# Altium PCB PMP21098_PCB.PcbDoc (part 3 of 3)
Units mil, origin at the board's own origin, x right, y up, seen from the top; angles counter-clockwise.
Board outline 5551.18 x 2125.98 mil, 4 copper layers (Top Layer, Signal Layer 1, Signal Layer 2, Bottom Layer), stack 61.6 mil thick; 197 components, 100 nets, 482 pads, 134 vias.
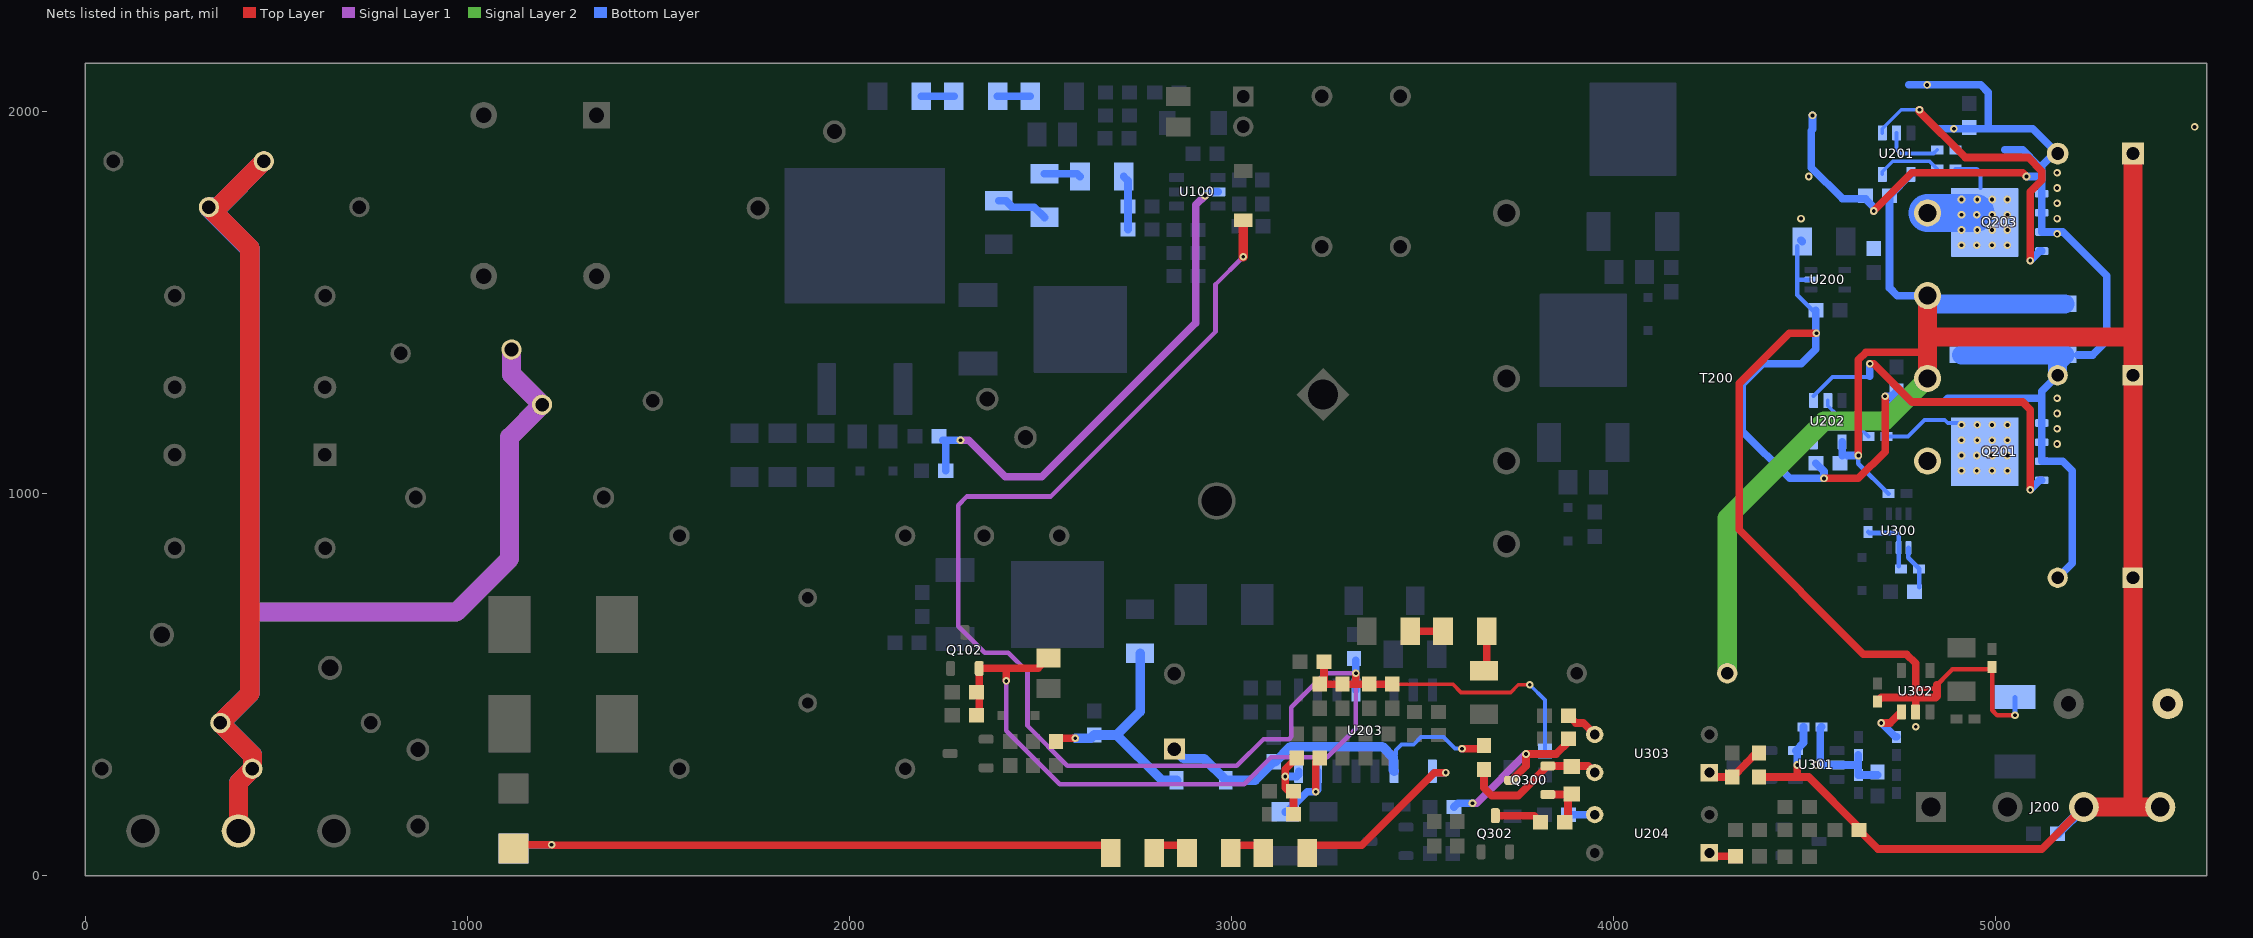
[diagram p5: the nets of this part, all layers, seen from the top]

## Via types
v1: diameter 20, hole 10, Top Layer to Bottom Layer, 134 vias

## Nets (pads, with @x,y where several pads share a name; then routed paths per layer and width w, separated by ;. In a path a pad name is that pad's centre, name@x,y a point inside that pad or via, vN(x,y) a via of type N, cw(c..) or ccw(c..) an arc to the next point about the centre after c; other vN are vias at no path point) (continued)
NetQ201_5: Q201.5 Q201.6 Q201.7 Q201.8 Q201.9@4970.43,1110 R203.2 T200.8 | length 207.1
  Bottom Layer w10: R203.2@4713.62,1150 4770,1150 4812.61,1192.61 4866.13,1192.61 4873.74,1185 Q201.8@4899.96,1185
  other v1: 4910,1060 4950,1060 4990,1060 5030,1060 4910,1100 4950,1100 4990,1100 5030,1100 4910,1140 4951.1,1140 4990,1140 5030,1140 4910,1180 4951.1,1180 4990,1180 5030,1180
NetQ203_5: Q203.5 Q203.6 Q203.7 Q203.8 Q203.9@4970.43,1710 R206.1 T200.11 | length 235
  Bottom Layer w10: R206.1@4893.62,1850 4950,1850 4960,1840 4960,1800
  Bottom Layer w100: T200.11@4821.18,1734.8 Q203.9@4945.63,1734.8
  other v1: 4910,1650 4950,1650 4990,1650 5030,1650 4910,1690 4951.1,1690 4990,1690 5030,1690 4910,1730 4950,1730 4990,1730 5030,1730 4910,1770 4951.1,1770 4990,1770 5030,1770
NetQ300_1: Q300.1 R309.1 R311.2 | length 139.5
  Top Layer w20: Q300.1@3827.24,212.6 R309.1@3884.09,212.6 ; R311.2@3880,140 3880,208.5 R309.1@3884.09,212.6 ; R309.1@3890,218.5 R309.1@3884.09,212.6
NetQ300_2: Q300.2 R304.2 R309.2 U303.4 | length 385.8
  Top Layer w20: R304.2@3660,278.5 3660,230.45 3680.45,210 3749.84,210 Q300.2@3827.24,287.4 3932.6,287.4 U303.4@3950,270
NetQ300_3: Q300.3 R313.1 R315.2 | length 462.6
  Top Layer w20: Q300.3@3732.93,250 Q300.3@3732.76,250 3770,287.24 v1(3770,318.9) 3848.9,318.9 3881.5,351.5 R315.2@3881.5,358.54
  Signal Layer 1 w20: v1(3630,190) 3641.1,190 v1(3770,318.9)
  Bottom Layer w20: R313.1@3581.5,180 3591.5,190 v1(3630,190)
NetQ302_3: Q302.3 R311.1 | length 125.6
  Top Layer w20: Q302.3@3690,157.24 3791.26,157.24 R311.1@3808.5,140
NetR100_1: R100.1 R101.2 | length 85.8
  Bottom Layer w20: R100.1@2187.09,2040 R101.2@2272.91,2040
NetR101_1: R101.1 R105.2 | length 85.8
  Bottom Layer w20: R101.1@2387.09,2040 R105.2@2472.91,2040
NetR102_1: R102.1 R107.1 U100.5 | length 1322
  Signal Layer 1 w20: v1(2290,1140) 2311.87,1140 2407.51,1044.36 2503.2,1044.36 2905.75,1446.91 2905.75,1755.75 v1(2930,1780)
  Bottom Layer w20: R102.1@2244.03,1140 v1(2290,1140) ; R107.1@2251.5,1060 R102.1@2251.5,1132.53 ; v1(2930,1780) 2940,1790 U100.5@2964.13,1790
NetR106_1: R106.1 R109.2 | length 138.3
  Bottom Layer w20: R106.1@2390,1767.09 2409.17,1767.09 2426.26,1750 2482.91,1750 R109.2@2510,1722.91
NetR109_1: R109.1 R115.2 | length 95.8
  Bottom Layer w20: R109.1@2510,1837.09 2595.83,1837.09 R115.2@2602.91,1830
NetR115_1: R115.1 R117.2 R118.2 | length 143.3
  Bottom Layer w20: R115.1@2717.09,1830 2728.5,1818.58 R118.2@2728.5,1751.46 R117.2@2728.5,1691.46
NetR214_1: R214.1 R220.2 | length 85.8
  Top Layer w20: R214.1@3467.09,640 R220.2@3552.91,640
NetR216_1: R216.1 U204.1 | length 59.6
  Top Layer w20: U204.1@4258.9,51.1 R216.1@4318.5,51.1
NetR217_1: R217.1 R218.2 | length 85.8
  Top Layer w20: R217.1@2797.09,80 R218.2@2882.91,80
NetR218_1: R218.1 R219.2 | length 85.8
  Top Layer w20: R218.1@2997.09,80 R219.2@3082.91,80
NetR219_1: R219.1 U203.1 | length 472.9
  Top Layer w20: R219.1@3197.09,80 3340,80 3530,270 v1(3560,270)
  Bottom Layer w20: U203.1@3528.7,270 v1(3560,270)
NetR220_1: R220.1 R223.2 | length 95.8
  Top Layer w20: R223.2@3667.09,544.17 R220.1@3667.09,640
NetR226_2: R226.2 U204.3 | length 68.5
  Bottom Layer w20: R226.2@3881.5,160 U204.3@3950,160
NetR300_2: R300.2 R301.2 U300.1 | length 116.2
  Bottom Layer w12: U300.1@4771.2,858.97 4771.2,841.2 4770,840 4770,832.5 R301.2@4799.23,803.27 R300.2@4799.23,755.39
NetR303_1: R303.1 R305.2 U303.1 | length 138
  Top Layer w20: U303.1@4261.5,258.5 R305.2@4310,258.5 4310.67,258.5 4346.57,294.41 4346.57,295.08 R303.1@4372.99,321.5
NetR310_1: R310.1 U302.1 | length 119.7
  Top Layer w20: v1(4700,400) 4723.58,400 U302.1@4752.6,429.02
  Bottom Layer w20: v1(4700,400) 4736.38,363.62 R310.1@4740,363.62
NetR316_2: R316.2 U303.3 | length 88.6
  Top Layer w20: R316.2@3881.5,418.54 3900.04,400 3920,400 U303.3@3950,370
OV: C234.1 R210.1 R211.2 U203.8 | length 207.2
  Top Layer w20: R210.1@3161.5,161.3 3161.5,208.5 3140,230 v1(3140,260) 3140,278.5 C234.1@3170,308.5
  Bottom Layer w20: v1(3140,260) U203.8@3170,260 ; U203.8@3175,265 U203.8@3175,273.7
PE: C100.2 C101.2 C102.2 C110.1 C111.1 C112.1 TP_PE.1 | length 10649.3
  Top Layer w50: C111.1@323.15,1750 430,1643.15 430,476.85 C110.1@353.15,400 436.85,316.3 C100.2@436.85,280 400.13,243.28 TP_PE.1@400.13,117.51 ; C111.1@346.85,1750 C101.2@466.85,1870
  Signal Layer 1 w50: TP_PE.1@400.13,117.51 400.13,243.28 C100.2@436.85,280 436.85,316.3 C110.1@353.15,400 430,476.85 430,680 ; C101.2@466.85,1870 346.85,1750 C111.1@323.15,1750 430,1643.15 430,680 ; C112.1@1115.02,1377.33 1115.02,1312.63 C102.2@1194.98,1232.67 1110,1147.69 1110,830 970,690 440,690 430,680
  Signal Layer 2 w50: TP_PE.1@400.13,117.51 400.13,243.28 C100.2@436.85,280 436.85,316.3 C110.1@353.15,400 430,476.85 430,690 ; C101.2@466.85,1870 346.85,1750 C111.1@323.15,1750 430,1643.15 430,690 ; C112.1@1115.02,1377.33 1115.02,1312.63 C102.2@1194.98,1232.67 1110,1147.69 1110,830 970,690 430,690
  Bottom Layer w50: C111.1@323.15,1750 323.15,1746.85 430,1640 430,476.85 C110.1@353.15,400 436.85,316.3 C100.2@436.85,280 400.13,243.28 TP_PE.1@400.13,117.51 ; C111.1@346.85,1750 C101.2@466.85,1870 ; C112.1@1115.02,1377.33 1115.02,1312.63 C102.2@1194.98,1232.67
RVCC: C116.1 C117.1 C228.1 C229.1 C230.1 C231.1 D109.2 Q102.2 R111.2 R212.1 R215.2 R225.2 U203.12 | length 5475.6
  Top Layer w10: C231.1@3420,501.5 3578.5,501.5 3600,480 3730,480 3750,500 v1(3780,500)
  Top Layer w20: R111.2@2339.05,427.56 Q102.2@2339.05,542.76 2410,542.76 ; v1(2410,510) 2410,542.76 ; C117.1@2520,570 2492.76,542.76 2410,542.76 ; 3241.5,540 3241.5,512.99 C228.1@3230,501.5 C229.1@3290,501.5 3325,501.5 ; v1(3325,530) 3325,501.5 ; C231.1@3420,501.5 C230.1@3360,501.5 3325,501.5
  Top Layer w25: v1(3030,1620) D109.2@3030,1715.53
  Signal Layer 1 w12: v1(2410,510) 2410,380 2550,240 3032.92,240 3102.79,309.87 3250,309.87 3325,384.87 v1(3325,530) 3245.12,530 3156.13,441.01 3156.13,363.75 3150,357.62 3083.01,357.62 3013.14,287.75 2569.78,287.75 2465.35,392.18 2465.35,533.84 2415.31,583.87 2353.31,583.87 2283.87,653.31 2283.87,970.11 2306.38,992.61 2526.38,992.61 2957.5,1423.73 2957.5,1547.5 v1(3030,1620)
  Bottom Layer w10: v1(3780,500) 3820,460 R215.2@3820,326.76
  Bottom Layer w20: U203.12@3325,486.3 v1(3325,530) R212.1@3325,563.5
SGND: C200.2 C202.1 C203.1 C204.2 C208.2 C209.2 C210.2 C211.2 C212.2 C216.2 C217.2 C218.2 C219.2 C300.2 C301.2 C303.2 C304.2 C305.2 Q201.1 Q201.2 Q201.3 Q203.1 Q203.2 Q203.3 R204.2 R207.1 R209.1 R301.1 R307.2 R312.1 U200.2 U300.2 U301.2 U302.2 | length 7503.4
  Top Layer w12: 4790,490 4835.46,490 4885.46,540 4983.62,540 R307.2@4990,546.38 4990,432.91 5002.91,420 v1(5050,420)
  Top Layer w20: v1(4530,1420) 4459.42,1420 4327.87,1288.45 4327.87,905.17 4653.04,580 4765.83,580 4790,555.83 4790,490 ; v1(4550,1040) 4640,1040 4710,1110 v1(4710,1255) ; v1(4680,1740) 4780,1840 5070,1840 v1(5080,1830) ; C305.2@4690,456.38 4700.2,466.57 4790,466.57 ; U302.2@4790,429.02 4790,466.57 ; 4845.59,499.87 4845.59,469.87 4842.29,466.57 4790,466.57
  Bottom Layer w12: C204.2@4480,1647.09 4480,1560 ; U200.2@4515.71,1560 4480,1560 ; C200.2@4528.5,1480 4520,1480 4480,1520 4480,1560 ; C300.2@4665.61,899.64 4668.18,897.08 4740,897.08 4745.61,891.47 U300.2@4745.61,858.97 R301.1@4745.61,809.64 ; v1(5050,420) R209.1@5050,467.4
  Bottom Layer w20: C204.2@4490,1662.91 C204.2@4492.91,1660 ; 4516.38,1950 4516.38,1853.62 4598.5,1771.5 4658.5,1771.5 4680,1750 v1(4680,1740) ; 4520,1953.62 v1(4520,1990) ; C219.2@4528.5,1080 4550,1058.5 v1(4550,1040) 4460,1040 4336.38,1163.62 4336.38,1286.38 4390,1340 4490,1340 4528.5,1378.5 C200.2@4528.5,1480 ; C301.2@4543.62,390 4540,386.38 4540,300 4550,290 U301.2@4584.13,290 4638,290 ; C304.2@4640,316.38 C303.2@4640,263.62 R312.1@4690,263.62 ; v1(4710,1255) 4726.5,1255 C218.2@4740,1268.5 4768.82,1239.68 ; 4730.31,1239.68 4768.82,1239.68 ; 4771.5,2070 v1(4820,2070) 4960,2070 4980,2050 4980,1955 ; 4847.28,1955 4980,1955 ; 5023.62,1900 5070,1900 5110,1860 ; v1(5080,1830) 5120.04,1830 ; C208.2@5151.57,1890 5120.04,1858.46 5120.04,1830 ; C210.2@5161.57,780 5200,818.43 5200,1060 5175,1085 Q201.3@5120.04,1085 Q201.2@5120.04,1135 Q201.1@5120.04,1185 5120.04,1250 ; C209.2@5161.57,1310 5120.04,1268.46 5120.04,1250 ; C208.2@5161.57,1890 5096.57,1955 4980,1955 ; 5214.65,1363.07 5253.07,1363.07 5290,1400 5290,1570 5175,1685 Q203.3@5120.04,1685 Q203.2@5120.04,1735 Q203.1@5120.04,1785 5120.04,1830 ; 4768.82,1239.68 4811.97,1239.68 4863.31,1239.68 4873.62,1250 5120.04,1250
  Bottom Layer w50: C202.1@4910,1363.07 C203.1@5000,1363.07 C211.2@5090,1363.07 C212.2@5180,1363.07 5161.57,1344.65 C209.2@5161.57,1310
  other v1: 4530,290 4790,390 5160,1130 5160,1170 5160,1210 5160,1250 5160,1680 4490,1720 5160,1720 5160,1760 5160,1800 4510,1830 5160,1840 4890,1955 5520,1960
VCC: C223.2 D205.2 R120.1 R231.1 | length 599.5
  Top Layer w20: R120.1@2548.5,360 v1(2590.26,360)
  Bottom Layer w25: v1(2590.26,360) 2631.5,360 C223.2@2640,368.5 2698.5,368.5 ; R231.1@2760,582.91 2760,430 2698.5,368.5 ; D205.2@2855.53,250 2817.01,250 2698.5,368.5
VCC_IC: C224.2 C226.1 D205.1 R304.1 U203.3 | length 961.9
  Top Layer w20: v1(3602.49,332.49) R304.1@3651,332.49
  Bottom Layer w10: 3422.5,310 3430,317.5 3430,329.47 3444.26,343.73 3476.27,343.73 3495.4,362.87 3554.6,362.87 3584.6,332.87 3589.93,332.87 3590.31,332.49 v1(3602.49,332.49)
  Bottom Layer w20: C224.2@3110,298.5 C224.2@3110.67,298.5
  Bottom Layer w25: C226.1@2850,331.57 2875.41,306.16 2928.31,306.16 D205.1@2984.47,250 3061.5,250 C224.2@3110,298.5 ; C224.2@3110.67,298.5 3114.21,298.5 3153.94,338.23 3394.27,338.23 3422.5,310 3422.5,276.2 U203.3@3425,273.7
VCR: C207.2 C233.1 U203.7 | length 250.3
  Top Layer w20: v1(3220,220) 3220,298.5 C233.1@3230,308.5
  Bottom Layer w20: C207.2@3140,167.09 3144.57,167.09 3197.48,220 v1(3220,220) 3225,225 U203.7@3225,273.7
VD_SR1: R206.2 U201.5 | length 170.1
  Bottom Layer w10: U201.5@4702.6,1835.87 4702.6,1842.6 4730,1870 4826.38,1870 R206.2@4846.38,1850
VD_SR2: R203.1 U202.5 | length 170.1
  Bottom Layer w10: U202.5@4522.6,1135.87 4522.6,1142.6 4550,1170 4646.38,1170 R203.1@4666.38,1150
VG_SR1: Q203.4 U201.1 | length 805.6
  Top Layer w20: v1(4799.81,2005) 4799.81,2000.19 4920,1880 5084.27,1880 5120.04,1844.23 5120.04,1820.04 5090,1790 v1(5090,1610)
  Bottom Layer w10: U201.1@4702.6,1944.13 4702.6,1955.26 4752.34,2005 v1(4799.81,2005)
  Bottom Layer w20: v1(5090,1610) 5115,1635 Q203.4@5120.04,1635
VG_SR2: Q201.4 U202.1 | length 917.7
  Top Layer w20: v1(4670,1340) 4680,1340 4780,1240 5070,1240 5090,1220 v1(5090,1010)
  Bottom Layer w10: U202.1@4522.6,1255.26 4572.34,1305 4667.28,1305
  Bottom Layer w20: 4670,1307.72 v1(4670,1340) ; v1(5090,1010) 5115,1035 Q201.4@5120.04,1035
Vout: C202.2 C203.2 C208.1 C209.1 C210.1 C211.1 C212.1 C213.2 C215.1 C217.1 C219.1 C301.1 J200.3 J200.4 R202.2 R213.1 R302.1 R303.2 T200.9 T200.10 TP200.1 U201.4 U202.4 U301.5 | length 6377.8
  Top Layer w20: R303.2@4380,258.5 4480,258.5 ; v1(4480,290) 4480,258.5 ; v1(4640,1100) 4640,1350 4660,1370 4821.18,1370 ; J200.3@5230,180 5120,70 4691.5,70 R213.1@4641.5,120 4641.5,127.05 4510.04,258.5 4480,258.5
  Top Layer w50: T200.9@4821.18,1301.73 4821.18,1370 4821.18,1410 ; T200.10@4821.18,1518.27 4821.18,1410 ; J200.3@5230,180 J200.4@5430,180 ; 5348.43,1410 4821.18,1410 ; 5358.43,181.57 C210.1@5358.43,780 C209.1@5358.43,1310 C208.1@5358.43,1890
  Signal Layer 2 w50: C215.1@4296.85,530 4296.85,936.85 4550,1190 4709.45,1190 T200.9@4821.18,1301.73
  Bottom Layer w12: v1(4640,1100) 4640,1078.82 R302.1@4718.82,1000
  Bottom Layer w20: U301.5@4475.87,327.4 4496.38,347.91 C301.1@4496.38,390 ; v1(4480,290) U301.5@4480,323.27 ; 4597.4,1100 U202.4@4597.4,1135.87 ; 4611.5,1100 v1(4640,1100) ; C217.1@4721.5,1780 4721.5,1538.5 4741.73,1518.27 T200.10@4821.18,1518.27 ; C217.1@4721.5,1780 U201.4@4777.4,1835.87
  Bottom Layer w25: C213.2@5161.5,110 J200.3@5230,178.5
  Bottom Layer w50: T200.10@4821.18,1518.27 4842.52,1496.93 C202.2@4910,1496.93 C203.2@5000,1496.93 C211.1@5090,1496.93 C212.1@5180,1496.93
VS_SR1: R207.2 U201.2 | length 158.8
  Bottom Layer w10: U201.2@4740,1944.13 4740,1900 4750,1890 4836.38,1890 R207.2@4846.38,1900
VS_SR2: R204.1 U202.2 | length 132.9
  Bottom Layer w10: U202.2@4560,1244.13 4560,1230 4585,1205 4661.38,1205 R204.1@4666.38,1200
XCAP: D106.1 D107.1 R217.2 | length 1641.7
  Top Layer w20: D107.1@1130,81.26 v1(1220,81.26) ; v1@1221.26,80 R217.2@2682.91,80
  Bottom Layer w20: D106.1@1130,81.26 v1(1220,81.26)
pads on no net: L100.4 L100.6 Q201.9@4954.88,1052.91 Q201.9@4954.88,1110 Q201.9@4954.88,1167.09 Q201.9@4988.35,1110 Q201.9@5024.96,1052.91 Q201.9@5024.96,1110 Q201.9@5024.96,1167.09 Q203.9@4954.88,1652.91 Q203.9@4954.88,1710 Q203.9@4954.88,1767.09 Q203.9@4988.35,1710 Q203.9@5024.96,1652.91 Q203.9@5024.96,1710 Q203.9@5024.96,1767.09 U200.1 U200.3 U300.5

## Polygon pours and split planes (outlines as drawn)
NetC106_2 on Top Layer "C106_2" (solid, remove dead copper, pour order 2): 960,190 930,220 930,480 1030,580 1030,860 1200,1030 1380,1030 1400,1010 1400,940 1240,780 1240,220 1210,190
NetC107_2 on Top Layer "C107_2" (solid, remove dead copper, pour order 10): 1340,750 1320,730 1320,580 1330,570 1520,570 1530,580 1530,730 1510,750
NetC108_2 on Top Layer "C108_2" (solid, remove dead copper, pour order 16): 2160,860 2180,880 2180,1010 2000,1190 2000,1990 1990,2000 1920,2000 1870,1950 1870,1040 2050,860
NetQ203_5 on Top Layer "Q203_5" (solid, remove dead copper, pour order 32): 4810,1810 4770,1770 4770,1610 4800,1580 5040,1580 5060,1600 5060,1800 5050,1810
NetQ201_5 on Top Layer "Q201_5" (solid, remove dead copper, pour order 36): 4790,1210 4770,1190 4770,1010 4790,990 5040,990 5060,1010 5060,1200 5050,1210
IN+ on Top Layer "IN+" (solid, remove dead copper, pour order 44): 4770,120 4750,140 4750,230 4830,310 5060,310 5080,330 5080,400 5180,500 5210,500 5240,470 5240,330 5130,220 5130,140 5110,120
Vout on Top Layer "Vout" (solid, remove dead copper, pour order 54): 4800,1560 4770,1530 4770,1290 4800,1260 5050,1260 5140,1350 5180,1350 5250,1280 5250,320 5150,220 5150,140 5170,120 5520,120 5540,140 5540,1890 5480,1950 5260,1950 5240,1930 5240,1680 5120,1560
SGND on Top Layer "SGND" (solid, remove dead copper, pour order 60): 5540,30 5520,10 4250,10 4230,30 4230,380 4270,420 4270,1300 4460,1490 4460,2080 4490,2110 5520,2110 5540,2090
GND on Top Layer "GND" (solid, remove dead copper, pour order 68): 3970,30 3950,10 3050,10 2870,190 1350,190 1320,220 1320,730 2700,2110 3030,2110 3970,1170
NetC102_1 on Bottom Layer "C102_1" (solid, remove dead copper, pour order 4): 1050,190 1040,200 1040,220 1039.67,220.33 1039.67,690.33 800,930 800,1080 810,1090 970,1090 1240,820 1240,220 1210,190
NetC107_2 on Bottom Layer "C107_2" (solid, remove dead copper, pour order 6): 1340,750 1320,730 1320,580 1330,570 1610,570 1940,240 2170,240 2190,260 2190,300 1740,750
NetC114_2 on Bottom Layer "C113_2" (solid, remove dead copper, pour order 12): 1700,1100 1680,1120 1680,1200 1830,1350 1960,1350 2050,1260 2050,1120 2030,1100
NetC108_2 on Bottom Layer "C108_2" (solid, remove dead copper, pour order 14): 1790,750 1790,730 1870,650 1950,650 2180,880 2180,900 2160,920 1960,920
NetC109_2 on Bottom Layer "C109_2" (solid, remove dead copper, pour order 18): 2280,1290 2260,1310 2260,1350 2150,1460 1740,1460 1650,1550 1650,1880 1870,2100 2085.43,2100 2110,2075.43 2110,1930 2130,1910 2270,1910 2290,1890 2290,1620 2340,1570 2370,1570 2390,1550 2390,1310 2370,1290
HV on Bottom Layer "HV" (solid, remove dead copper, pour order 20): 2350,1690 2340,1680 2340,1630 2380,1590 2410,1590 2440,1560 2440,1300 2560,1180 3260,1180 3490,1410 3490,1640 3670,1820 4190,1820 4210,1840 4210,2090 4190,2110 3670,2110 3314.77,1754.77 3314.77,1484.77 3260,1430 2860,1430 2700,1590 2520,1590 2420,1690
HS on Bottom Layer "HS" (solid, remove dead copper, pour order 22): 3890,1750 3780,1640 3780,1470 3660,1350 3660,1280 3680,1260 4030,1260 4050,1280 4050,1510 4030,1530 4030,1710 3990,1750
Vout on Bottom Layer "Vout" (solid, remove dead copper, pour order 26): 4780,1290 4800,1270 4850,1270 4860,1280 4860,1410 4880,1430 5200,1430 5220,1450 5220,1520 5180,1560 4790,1560 4750,1600 4750,1682.6 4732.6,1700 4600,1700 4590,1690 4590,1580 4595.59,1585.59 4604.41,1585.59 4650,1540 4650,1430 4670,1410 4730,1410 4780,1360
NetQ203_5 on Bottom Layer "Q203_5" (solid, remove dead copper, pour order 28): 4810,1810 4770,1770 4770,1610 4800,1580 5040,1580 5060,1600 5060,1800 5050,1810
NetQ201_5 on Bottom Layer "Q201_5" (solid, remove dead copper, pour order 42): 5060,1010 5060,1200 5050,1210 4890,1210 4860,1180 4833.78,1180 4823.78,1170 4823.78,1150 4821.65,1150 4801.65,1130 4800,1130 4770,1100 4770,1050 4830,990 5040,990
IN+ on Bottom Layer "IN+" (solid, remove dead copper, pour order 46): 4770,120 4750,140 4750,230 4830,310 5060,310 5080,330 5080,400 5180,500 5210,500 5240,470 5240,330 5130,220 5130,140 5110,120
SGND on Bottom Layer "SGND" (solid, remove dead copper, pour order 62): 5540,30 5520,10 4250,10 4230,30 4230,380 4270,420 4270,1300 4460,1490 4460,2080 4490,2110 5520,2110 5540,2090
GND on Bottom Layer "GND" (solid, remove dead copper, pour order 70): 3970,30 3950,10 3050,10 2870,190 1350,190 1320,220 1320,730 2700,2110 3030,2110 3970,1170
NetC103_2 on Bottom Layer "C103_2" (solid, pour order 58): 2420,620 2440,600 2650,600 2660,610 2660,750 2730,820 2950,820 3020,890 3020,1000 2980,1040 2640,1040 2420,820
NetC107_2 on Signal Layer 1 "C107_2" (solid, remove dead copper, pour order 8): 1340,750 1320,730 1320,580 1330,570 1610,570 1940,240 2170,240 2190,260 2190,300 1740,750
NetQ203_5 on Signal Layer 1 "Q203_5" (solid, remove dead copper, pour order 30): 4810,1810 4770,1770 4770,1610 4800,1580 5040,1580 5060,1600 5060,1800 5050,1810
NetQ201_5 on Signal Layer 1 "Q201_5" (solid, remove dead copper, pour order 40): 4790,1210 4770,1190 4770,1010 4790,990 5040,990 5060,1010 5060,1200 5050,1210
IN+ on Signal Layer 1 "IN+" (solid, remove dead copper, pour order 50): 4770,120 4750,140 4750,230 4830,310 5060,310 5080,330 5080,400 5180,500 5210,500 5240,470 5240,330 5130,220 5130,140 5110,120
SGND on Signal Layer 1 "SGND" (solid, remove dead copper, pour order 66): 5540,30 5520,10 4250,10 4230,30 4230,380 4270,420 4270,1300 4460,1490 4460,2080 4490,2110 5520,2110 5540,2090
GND on Signal Layer 1 "GND" (solid, remove dead copper, pour order 74): 3970,30 3950,10 3050,10 2870,190 1350,190 1320,220 1320,730 2700,2110 3030,2110 3970,1170
NetQ203_5 on Signal Layer 2 "Q203_5" (solid, remove dead copper, pour order 34): 4810,1810 4770,1770 4770,1610 4800,1580 5040,1580 5060,1600 5060,1800 5050,1810
NetQ201_5 on Signal Layer 2 "Q201_5" (solid, remove dead copper, pour order 38): 4830,1210 4770,1150 4770,1010 4790,990 5040,990 5060,1010 5060,1200 5050,1210
IN+ on Signal Layer 2 "IN+" (solid, remove dead copper, pour order 48): 4770,120 4750,140 4750,230 4830,310 5060,310 5080,330 5080,400 5180,500 5210,500 5240,470 5240,330 5130,220 5130,140 5110,120
Vout on Signal Layer 2 "Vout" (solid, remove dead copper, pour order 56): 4800,1560 4770,1530 4770,1290 4800,1260 5050,1260 5140,1350 5180,1350 5250,1280 5250,320 5150,220 5150,140 5170,120 5520,120 5540,140 5540,1890 5480,1950 5260,1950 5240,1930 5240,1680 5120,1560
SGND on Signal Layer 2 "SGND" (solid, remove dead copper, pour order 64): 5540,30 5520,10 4250,10 4230,30 4230,380 4270,420 4270,1300 4460,1490 4460,2080 4490,2110 5520,2110 5540,2090
GND on Signal Layer 2 "GND" (solid, remove dead copper, pour order 72): 3970,30 3950,10 3050,10 2870,190 1350,190 1320,220 1320,730 2700,2110 3030,2110 3970,1170

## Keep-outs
Keep-Out Layer:
  text ".Layer_Name" at 577,-858.49 h60

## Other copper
Top Layer:
  text ".Layer_Name" at 577,-858.49 h60
Bottom Layer:
  text ".Layer_Name" at 577,-858.49 h60

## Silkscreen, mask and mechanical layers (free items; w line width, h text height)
Top Overlay:
  lines w10: 2860,1840 2870,1840 2940,1910 ; 3100,740 3100,530 3130,500 ; 3210,200 3220,190 3220,180 ; 3250,740 3330,740 3440,850 3440,960 3350,1050 3100,1050 3080,1050 3054,1024 3054,954 3010,910 3010,760 3030,740 3260,740 ; 3520,20 3630,20 3640,30 ; 3760,560 3730,530 3730,420 3770,380 ; 3930,240 3970,240 3990,260 3990,300 ; 4410,370 4410,430 4410,450 4440,480 4640,480 ; 4420,310 4490,310 4680,310 4680,400 ; 4520,230 4520,310 ; 4990,410 5010,430 5030,430
  text "PMP21251 RevB" at 1270,20 h108.27
  text ".Layer_Name" at 577,-858.49 h60
Bottom Overlay:
  lines w10: 1900,2045 2005,2045 ; 2470,10 2470,120 2490,140 2570,140 2620,190 2720,190 2880,190 2880,10 ; 2820,2090 2830,2090 2850,2110 3080,2110 3120,2070 3120,2040 3190,1970 ; 2880,80 3070,80 ; 2970,1670 2970,1600 2990,1580 ; 3190,1310 3170,1310 3130,1270 3130,1230 3110,1210 2999.19,1210 2850,1359.19 2850,1450 2880,1480 2940,1480 2980,1520 2980,1570 3000,1590 3210,1590 3260,1540 3260,1360 ; 4210,20 4270,20 ; 4220,120 4270,120 ; 4610,2050 4640,2050 4700,1990 ; 1460,2010 1900,2010 1900,2080 1460,2080 1460,2010 ; 3180,1760 3200,1740 3310,1740 3330,1760 3330,1790 3370,1830 3520,1830 3540,1850 3540,1940 3510,1970 3500,1980 3200,1980 3180,1960 3180,1850 3180,1760
  text ".Layer_Name" at 577,-858.49 h60
Top Paste:
  text ".Layer_Name" at 577,-858.49 h60
Bottom Paste:
  text ".Layer_Name" at 577,-858.49 h60
Top Solder:
  text ".Layer_Name" at 577,-858.49 h60
  text ".Layer_Name" at 577,-858.49 h60
Bottom Solder:
  rectangle: 3780,1610 3910,1710
  rectangle: 3640,1830 3820,2070
  text ".Layer_Name" at 577,-858.49 h60
Drill Guide:
  text ".Layer_Name" at 577,-858.49 h60
M1 Board Outline:
  lines w7.01: 0,2125.98 0,0 5551.18,0 5551.18,2125.98 ; 60,2125.98 5611.18,2125.98
  text ".Layer_Name" at 577,-858.49 h60
M2 Board Dimensions:
  rectangle: 125,-400 500,-275
  rectangle: 0,-275 125,-150
  lines w7: 0,-275 1000,-275 ; 125,-400 125,-150 ; 250,-400 250,-150 ; 500,-400 500,-150 ; 750,-400 750,-150 ; 0,-400 0,-150 1000,-150 1000,-400 0,-400
  text ".Layer_Name" at 577,-858.49 h60
M3 3D STEP Top:
  text ".Layer_Name" at 577,-858.49 h60
M4 3D STEP Bottom:
  text ".Layer_Name" at 577,-858.49 h60
M5 Assembly Top:
  lines w10: -292,-930.17 6308,-930.17 ; -292,-726.83 6310,-726.83 ; -292,-523.5 -292,-1133.5 3713,-1133.5 6310,-1133.5 6310,-523.5 -291.5,-523.5 -291.5,-1133.5 1284,-1133.5 ; 2173,-1133.5 2173,-523.5 ; 3440,-726.83 3440,-523.5 ; 4280,-726.83 4280,-523.5 ; 4902,-1140 4902,-937.17
  text "COMPONENTS MARKED 'DNP' SHOULD NOT BE POPULATED." at 1153.5,-318.5 h60
  text "ASSEMBLY VARIANT:" at 1153,-434 h60
  text ".VariantName" at 2189,-434 h60
  text "PCB VIEWED FROM TOP SIDE" at -228.5,-655.67 h60
  text "BOARD #:" at 2248,-655.67 h60
  text ".PRJ_Number" at 2793.5,-655.67 h60
  text "REV:" at 3638,-655.67 h60
  text ".PCB_Rev" at 3929.5,-655.67 h60
  text "SVN REV:" at 4476,-655.67 h60
  text ".VersionControl_RevNumber" at 4982,-655.67 h60
  text "TID #:" at 2248,-859 h60
  text ".TID" at 2793.5,-859 h60
  text "PLOT NAME =" at -228.5,-1064.34 h60
  text ".plot_File_Name" at 577,-1064.34 h60
  text "GENERATED    :" at 2250,-1064.34 h60
  text ".Print_Date" at 3119.5,-1064.34 h60
  text ".Print_Time" at 3848.5,-1064.34 h60
  text "TEXAS INSTRUMENTS" at 5113,-1064.34 h60
M6 Assembly Bottom:
  lines w10: -292.5,-727.33 6309.5,-727.33 ; -290.5,-930.67 6309.5,-930.67 ; 1115.5,-1140.5 1115.5,-937.67 ; 1737.5,-727.33 1737.5,-524 ; 2577.5,-727.33 2577.5,-524 ; 3844.5,-1134 3844.5,-524 ; 4733.5,-1134 6309,-1134 6309,-524 -292.5,-524 -292.5,-1134 2304.5,-1134 6309.5,-1134 6309.5,-524
  text "COMPONENTS MARKED 'DNP' SHOULD NOT BE POPULATED." at 6102,-318 h60
  text ".VariantName" at 5058,-434 h60
  text "ASSEMBLY VARIANT:" at 6097,-434 h60
  text ".VersionControl_RevNumber" at 1035.5,-656.17 h60
  text "SVN REV:" at 1541.5,-656.17 h60
  text ".PCB_Rev" at 2088,-656.17 h60
  text "REV:" at 2379.5,-656.17 h60
  text ".PRJ_Number" at 3224,-656.17 h60
  text "BOARD #:" at 3769.5,-656.17 h60
  text "PCB VIEWED FROM BOTTOM SIDE" at 6246,-656.17 h60
  text ".TID" at 3224,-859.5 h60
  text "TID #:" at 3769.5,-859.5 h60
  text "TEXAS INSTRUMENTS" at 904.5,-1064.84 h60
  text ".Print_Time" at 2169,-1064.84 h60
  text ".Print_Date" at 2898,-1064.84 h60
  text "GENERATED    :" at 3767.5,-1064.84 h60
  text ".plot_File_Name" at 5440.5,-1064.84 h60
  text "PLOT NAME =" at 6246,-1064.84 h60
M9 Title Sheet:
  drawing of 57 lines, arcs and shapes, not listed
  text "1" at 739.84,8036.5 h70
  text "2" at 3235.5,8036.5 h70
  text "3" at 5724.84,8036.5 h70
  text "4" at 8231.51,8036.5 h70
  text "5" at 10730.5,8036.5 h70
  text "6" at 13235.5,8036.5 h70
  text "A" at -416.5,6893.5 h70
  text "A" at 14383.5,6893.5 h70
  text "B" at -416.5,4513.5 h70
  text "B" at 14383.5,4513.5 h70
  text "C" at -416.5,2138.5 h70
  text "C" at 14383.5,2138.5 h70
  text "PROJECT TITLE:" at 11343.5,277.5 h45
  text ".PRJ_Title" at 11393.5,144.17 h70
  text "DESIGNED FOR:" at 11343.5,-23.5 h45
  text ".PRJ_Customer" at 11393.5,-163.5 h70
  text "D" at -416.5,-231.5 h70
  text "D" at 14383.5,-231.5 h70
  text "FILE NAME:" at 11343.5,-323.5 h45
  text ".PCB_File_Name_No_Path" at 11393.5,-443.5 h70
  text "Texas Instruments (TI) and/or its licensors do not warrant the accuracy or completeness of this specification" at 6374,-605.34 h45
  text "ENGINEER:" at 11343.5,-613.5 h45
  text "LAYOUT BY:" at 12848.5,-613.5 h45
  text "or any information contained therein. TI and/or its licensors do not warrant that this design will meet" at 6329.01,-718 h45
  text ".PRJ_Engineer" at 11393.5,-768.49 h70
  text ".PCB_Layout" at 12899,-768.49 h70
  text "the specifications, will be suitable for your application or fit for any particular purpose, or will operate in" at 6329.01,-830.67 h45
  text ".Layer_Name" at 577,-858.49 h60
  text "ALTIUM DESIGNER VERSION:" at 12848.5,-923.5 h45
  text "an implementation. TI and/or its licensors do not warrant that the design is production worthy. You should" at 6329.01,-943.33 h45
  text "completely validate and test your design implementation to confirm the system functionality for your application." at 6374,-1056 h45
  text ".print_Scale" at 11393.5,-1056.83 h70
  text ".Application_BuildNumber" at 12899,-1056.83 h70
  text "1" at 739.84,-1263.5 h70
  text "2" at 3235.5,-1263.5 h70
  text "3" at 5724.84,-1263.5 h70
  text "4" at 8231.51,-1263.5 h70
  text "5" at 10730.5,-1263.5 h70
  text "6" at 13235.5,-1263.5 h70
M10 Fab Notes:
  drawing of 173 lines, arcs and shapes, not listed
  text "DESIGN INFORMATION" at 12378.02,6201 h60
  text "MIN. TRACK WIDTH:" at 11733.46,6021 h60
  text "10" at 12829.7,6021 h60
  text "MIL" at 12984.46,6021 h60
  text "MIN. CLEARANCE:" at 11733.46,5889 h60
  text "0.2" at 12769.7,5889 h60
  text "mm" at 12984.46,5889 h60
  text "MIN. VIA PAD SIZE:" at 11733.46,5757 h60
  text "20" at 12799.71,5757 h60
  text "MIL" at 12984.46,5757 h60
  text "0.05mm (2MIL)" at 12428.46,5615.29 h60
  text "MINIMUM ANNULAR RING" at 11404.23,5611 h60
  text "EXTERNAL" at 13136.46,5611 h60
  text "PER" at 11604.23,5493 h60
  text "IPC-D-275 CLASS 2 LEVEL C" at 11824.23,5493 h60
  text "MIL, HOLES" at 13312.46,5380.71 h60
  text "+/-" at 12920,5380 h60
  text "+/-" at 13774,5380 h60
  text "REGISTRATION TOLERANCES:" at 11404.23,5375 h60
  text "METAL" at 12604,5375 h60
  text "5" at 13180.2,5375 h60
  text "3" at 14013.2,5375 h60
  text "MIL" at 14129.46,5375 h60
  text "+/-" at 13774,5262 h60
  text "HOLE SIZE TOLERANCE (UNLESS OTHERWISE SPECIFIED):" at 11404.23,5257 h60
  text "3" at 14013.2,5257 h60
  text "MIL" at 14129.46,5257 h60
  text "MATERIAL:" at 11329.46,5047.54 h60
  text "FR-4 High Tg" at 12315.9,4907.21 h60
  text "FR-408" at 11750.46,4898.64 h60
  text "OTHER" at 13238.46,4898.64 h60
  text "X" at 12161,4895 h60
  text "62 MIL (1.6mm) +/-10%" at 12070.56,4735.92 h60
  text "THICKNESS:" at 11404.23,4731.64 h60
  text "X" at 11942.4,4731.64 h60
  text "OTHER" at 13355.46,4731.64 h60
  text "TOLERANCE:" at 11404.23,4573.64 h60
  text "X" at 12243.53,4573.64 h60
  text "ANSI IPC-6012 TYPE 3 CLASS 2" at 12430.48,4573.64 h60
  text "OTHER +/-" at 12430.46,4417.64 h60
  text "BOW & TWIST:" at 11404.23,4260.64 h60
  text "X" at 12243.53,4260.64 h60
  text "ANSI IPC-6012 TYPE 3 CLASS 2" at 12430.48,4260.64 h60
  text "OTHER +/-" at 12430.46,4102.13 h60
  text "DRILLING:" at 11329.46,3963.64 h60
  text "REFERENCE:" at 11404.23,3846.64 h60
  text "X" at 12052.46,3846.64 h60
  text "AS SHOWN" at 12239.46,3846.64 h60
  text "X" at 12953.46,3846.64 h60
  text "NC_DRILL FILES" at 13090.46,3846.64 h60
  text "PTH COPPER THICKNESS:" at 11404.23,3688.64 h60
  text "X" at 12534.46,3688.64 h60
  text "20-30 um" at 12671.46,3688.64 h60
  text "OTHER" at 13388.46,3688.64 h60
  text "BOARD FINISH:" at 11329.46,3529.64 h60
  text "SILKSCREEN:" at 11484.68,3411.64 h60
  text "X" at 12433.46,3411.64 h60
  text "TOP" at 12559.46,3411.64 h60
  text "X" at 12943.46,3411.64 h60
  text "BOTTOM" at 13070.46,3411.64 h60
  text "SILKSCREEN COLOR:" at 11484.68,3244.64 h60
  text "X" at 12432.42,3244.64 h60
  text "WHITE" at 12559.46,3244.64 h60
  text "OTHER" at 13070.46,3244.64 h60
  text "X" at 12563.42,3085.44 h60
  text "GREEN" at 12690.46,3085.44 h60
  text "OTHER" at 13308.46,3085.44 h60
  text "SOLDER RESIST COLOR:" at 11484.68,3074.64 h60
  text "X" at 12563.42,2915.44 h60
  text "MATTE" at 12690.46,2915.44 h60
  text "SEMI-GLOSS" at 13308,2914.8 h60
  text "IMMERSION GOLD (ENIG)" at 12390.46,2726.92 h60
  text "ENEPIG" at 13728,2723.64 h60
  text "SURFACE FINISH:" at 11329.46,2722.64 h60
  text "IMM. TIN/SILVER OR EQUIV" at 11659,2565.64 h60
  text "OTHER" at 13090.46,2565.64 h60
  text "X" at 11500,2560 h60
  text "ARRAY/PANEL:" at 11329.46,2386.64 h60
  text "CUT AND TRIM PER M1 BOARD OUTLINE" at 12390.46,2382.35 h60
  text "N.C. ROUTE" at 12390.46,2230.64 h60
  text "X" at 13069.46,2230.64 h60
  text "V. SCORE" at 13256.46,2230.64 h60
  text "CERTIFICATION:" at 11329.46,2093.64 h60
  text "MATERIALS AND WORKMANSHIP FOR ALL PCBS" at 12054.46,2093.64 h60
  text "TO MEET OR EXCEED THE REQUIREMENTS OF:" at 12054.46,1995.64 h60
  text "X" at 11680.96,1859.13 h60
  text "ANSI IPC-A-600F CLASS ->" at 11819.96,1859.13 h60
  text "X" at 13459.02,1859.13 h60
  text "2" at 13577.96,1859.14 h60
  text "1" at 13262.96,1857.64 h60
  text "3" at 13931.96,1857.64 h60
  text "X" at 12495.02,1699.64 h60
  text "RoHS" at 12631.96,1699.64 h60
  text "OTHER" at 13276.36,1699.64 h60
  text "PER ORDER" at 13673.42,1699.64 h60
  text "ALL BOARDS MUST MEET OR EXCEED UL94-V0 REQUIREMENTS." at 11357,1534 h60
  text "PCB MUST BEAR THE UL94V-0 UL REGISTERED MATERIAL ID NUMBER" at 11357,1414 h60
  text "ADDITIONAL REQUIREMENTS:" at 11329.46,1240.64 h60
  text "MICROSECTION:" at 11404.23,1125.64 h60
  text "YES" at 12309.96,1125.64 h60
  text "X" at 12580,970 h60
  text "REQUIRED" at 13171.46,969.49 h60
  text "BARE BOARD ELEC. TEST:" at 11404.23,966.64 h60
  text "NONE" at 12709.96,966.64 h60
  text "PER ORDER" at 13763.46,966.64 h60
  text ".Layer_Name" at 577,-858.49 h60
M11 Gerber Information:
  lines w10: -292,-930.17 6308,-930.17 ; -292,-726.83 6310,-726.83 ; -292,-523.5 -292,-1133.5 3713,-1133.5 6310,-1133.5 6310,-523.5 -291.5,-523.5 -291.5,-1133.5 1284,-1133.5 ; 2173,-1133.5 2173,-523.5 ; 3440,-726.83 3440,-523.5 ; 4280,-726.83 4280,-523.5 ; 4902,-1140 4902,-937.17
  text "ALL ARTWORK VIEWED FROM TOP SIDE" at -228.5,-655.67 h60
  text "BOARD #:" at 2248,-655.67 h60
  text ".PRJ_Number" at 2793.5,-655.67 h60
  text "REV:" at 3638,-655.67 h60
  text ".PCB_Rev" at 3929.5,-655.67 h60
  text "SVN REV:" at 4476,-655.67 h60
  text ".VersionControl_RevNumber" at 4982,-655.67 h60
  text "LAYER NAME =" at -228.5,-858.49 h60
  text "TID #:" at 2248,-859 h60
  text ".TID" at 2793.5,-859 h60
  text "PLOT NAME =" at -228.5,-1064.34 h60
  text ".plot_File_Name" at 577,-1064.34 h60
  text "GENERATED    :" at 2250,-1064.34 h60
  text ".Print_Date" at 3119.5,-1064.34 h60
  text ".Print_Time" at 3848.5,-1064.34 h60
  text "TEXAS INSTRUMENTS" at 5113,-1064.34 h60
M12 Stackup:
  drawing of 295 lines, arcs and shapes, not listed
  text "Layer" at 5837.5,1347.5 h60
  text "Name" at 6247.41,1347.5 h60
  text "Material" at 7187.15,1347.5 h60
  text "Thickness" at 8046.92,1347.5 h60
  text "Constant" at 8696.76,1347.5 h60
  text "Board Layer Stack" at 9266.62,1347.5 h60
  text "1" at 5837.5,1227.5 h60
  text "Top Overlay" at 6247.41,1227.5 h60
  text "2" at 5837.5,1107.5 h60
  text "Top Solder" at 6247.41,1107.5 h60
  text "Solder Resist" at 7187.15,1107.5 h60
  text "0.40mil" at 8046.92,1107.5 h60
  text "3.5" at 8696.76,1107.5 h60
  text "3" at 5837.5,987.5 h60
  text "Top Layer" at 6247.41,987.5 h60
  text "Copper" at 7187.15,987.5 h60
  text "1.40mil" at 8046.92,987.5 h60
  text "4" at 5837.5,867.5 h60
  text "Dielectric 2" at 6247.41,867.5 h60
  text "8.00mil" at 8046.92,867.5 h60
  text "4.2" at 8696.76,867.5 h60
  text "5" at 5837.5,747.5 h60
  text "Signal Layer 1" at 6247.41,747.5 h60
  text "Copper" at 7187.15,747.5 h60
  text "1.40mil" at 8046.92,747.5 h60
  text "6" at 5837.5,627.5 h60
  text "Dielectric1" at 6247.41,627.5 h60
  text "FR-4" at 7187.15,627.5 h60
  text "40.00mil" at 8046.92,627.5 h60
  text "4.8" at 8696.76,627.5 h60
  text "7" at 5837.5,507.5 h60
  text "Signal Layer 2" at 6247.41,507.5 h60
  text "Copper" at 7187.15,507.5 h60
  text "1.40mil" at 8046.92,507.5 h60
  text "8" at 5837.5,387.5 h60
  text "Dielectric 3" at 6247.41,387.5 h60
  text "8.00mil" at 8046.92,387.5 h60
  text "4.2" at 8696.76,387.5 h60
  text "9" at 5837.5,267.5 h60
  text "Bottom Layer" at 6247.41,267.5 h60
  text "Copper" at 7187.15,267.5 h60
  text "1.40mil" at 8046.92,267.5 h60
  text "10" at 5837.5,147.5 h60
  text "Bottom Solder" at 6247.41,147.5 h60
  text "Solder Resist" at 7187.15,147.5 h60
  text "0.40mil" at 8046.92,147.5 h60
  text "3.5" at 8696.76,147.5 h60
  text "11" at 5837.5,27.5 h60
  text "Bottom Overlay" at 6247.41,27.5 h60
  text ".Layer_Name" at 577,-858.49 h60
M13 Component Bodies Top:
  text ".Layer_Name" at 577,-858.49 h60
M14 Component Bodies Bottom:
  text ".Layer_Name" at 577,-858.49 h60
M15 Courtyards Top:
  text ".Layer_Name" at 577,-858.49 h60
M16 Courtyards Bottom:
  text ".Layer_Name" at 577,-858.49 h60
Drill Drawing:
  circle w10: c5853.72,2416.04 r16.58
  circle w10: c5853.72,2416.04 r27.63
  circle w10: c5853.72,1794.44 r27.63
  lines w10: 5826.09,1891.14 5826.09,1904.95 5839.9,1918.76 5826.09,1932.58 5826.09,1946.39 5839.9,1946.39 5853.72,1932.58 5867.53,1946.39 5881.34,1946.39 5881.34,1932.58 5867.53,1918.76 5881.34,1904.95 5881.34,1891.14 5867.53,1891.14 5853.72,1904.95 5839.9,1891.14 5826.09,1891.14 ; 5826.09,2139.78 5881.34,2139.78 5881.34,2195.03 5826.09,2195.03 5826.09,2139.78 ; 5826.09,2264.1 5853.72,2277.91 5881.34,2264.1 5867.53,2291.72 5881.34,2319.35 5853.72,2305.54 5826.09,2319.35 5839.9,2291.72 5826.09,2264.1 ; 5826.09,2526.55 5839.9,2526.55 5853.72,2512.74 5867.53,2526.55 5881.34,2526.55 5867.53,2540.36 5881.34,2554.18 5867.53,2554.18 5853.72,2567.99 5839.9,2554.18 5826.09,2554.18 5839.9,2540.36 5826.09,2526.55 ; 5826.09,2637.06 5853.72,2650.87 5881.34,2637.06 5867.53,2664.68 5881.34,2692.31 5853.72,2678.5 5826.09,2692.31 5839.9,2664.68 5826.09,2637.06 ; 5826.09,2789 5853.72,2761.38 5881.34,2789 5853.72,2816.63 5826.09,2789 ; 5826.09,2899.51 5839.9,2899.51 5853.72,2885.7 5867.53,2899.51 5881.34,2899.51 5867.53,2913.32 5881.34,2927.14 5867.53,2927.14 5853.72,2940.95 5839.9,2927.14 5826.09,2927.14 5839.9,2913.32 5826.09,2899.51 ; 5826.09,3023.83 5839.9,3023.83 5839.9,3010.02 5867.53,3010.02 5867.53,3023.83 5881.34,3023.83 5881.34,3051.46 5867.53,3051.46 5867.53,3065.27 5839.9,3065.27 5839.9,3051.46 5826.09,3051.46 5826.09,3023.83 ; 5826.09,3134.34 5881.34,3134.34 5881.34,3189.59 5826.09,3189.59 5826.09,3134.34 ; 5826.09,3313.91 5881.34,3313.91 5853.72,3258.66 5826.09,3313.91 ; 5837.14,2150.83 5870.29,2150.83 5870.29,2183.98 5837.14,2183.98 5837.14,2150.83 ; 5837.14,2275.15 5853.72,2283.43 5870.29,2275.15 5862.01,2291.72 5870.29,2308.3 5853.72,2300.01 5837.14,2308.3 5845.43,2291.72 5837.14,2275.15 ; 5837.14,2905.03 5845.43,2905.03 5853.72,2896.75 5862.01,2905.03 5870.29,2905.03 5862.01,2913.32 5870.29,2921.61 5862.01,2921.61 5853.72,2929.9 5845.43,2921.61 5837.14,2921.61 5845.43,2913.32 5837.14,2905.03
  lines w12: 5776,1729.52 9007.49,1729.52 ; 5776,3345.68 9007.49,3345.68 ; 6113.86,1605.2 6113.86,3470 ; 6445.86,1605.2 6445.86,3470 ; 7082.43,1605.2 7082.43,3470 ; 7341.57,1605.2 7341.57,3470 ; 7716.72,1605.2 7716.72,3470 ; 8441.05,1605.2 8441.05,3470 ; 5776,1605.2 9007.49,1605.2 9007.49,3470 5776,3470 5776,1605.2
  text "Symbol" at 5850.59,3382.98 h72
  text "Quantity" at 6151.16,3382.98 h72
  text "Finished Hole Size" at 6483.16,3382.98 h72
  text "Plated" at 7119.72,3382.98 h72
  text "Hole Type" at 7378.86,3382.98 h72
  text "Drill Layer Pair" at 7754.02,3382.98 h72
  text "Hole Tolerance" at 8478.35,3382.98 h72
  text "134" at 6151.16,3258.66 h60
  text "10.00mil (0.254mm)" at 6483.16,3258.66 h60
  text "PTH" at 7119.72,3258.66 h60
  text "Round" at 7378.86,3258.66 h60
  text "Top Layer - Bottom Layer" at 7754.02,3258.66 h60
  text "8" at 6151.16,3134.34 h60
  text "25.59mil (0.650mm)" at 6483.16,3134.34 h60
  text "PTH" at 7119.72,3134.34 h60
  text "Round" at 7378.86,3134.34 h60
  text "Top Layer - Bottom Layer" at 7754.02,3134.34 h60
  text "2" at 6151.16,3010.02 h60
  text "29.53mil (0.750mm)" at 6483.16,3010.02 h60
  text "PTH" at 7119.72,3010.02 h60
  text "Round" at 7378.86,3010.02 h60
  text "Top Layer - Bottom Layer" at 7754.02,3010.02 h60
  text "16" at 6151.16,2885.7 h60
  text "33.47mil (0.850mm)" at 6483.16,2885.7 h60
  text "PTH" at 7119.72,2885.7 h60
  text "Round" at 7378.86,2885.7 h60
  text "Top Layer - Bottom Layer" at 7754.02,2885.7 h60
  text "28" at 6151.16,2761.38 h60
  text "35.43mil (0.900mm)" at 6483.16,2761.38 h60
  text "PTH" at 7119.72,2761.38 h60
  text "Round" at 7378.86,2761.38 h60
  text "Top Layer - Bottom Layer" at 7754.02,2761.38 h60
  text "2" at 6151.16,2637.06 h60
  text "39.37mil (1.000mm)" at 6483.16,2637.06 h60
  text "PTH" at 7119.72,2637.06 h60
  text "Round" at 7378.86,2637.06 h60
  text "Top Layer - Bottom Layer" at 7754.02,2637.06 h60
  text "4" at 6151.16,2512.74 h60
  text "39.37mil (1.000mm)" at 6483.16,2512.74 h60
  text "PTH" at 7119.72,2512.74 h60
  text "Round" at 7378.86,2512.74 h60
  text "Top Layer - Bottom Layer" at 7754.02,2512.74 h60
  text "+/-1.18mil" at 8478.35,2512.74 h60
  text "6" at 6151.16,2388.42 h60
  text "40.00mil (1.016mm)" at 6483.16,2388.42 h60
  text "PTH" at 7119.72,2388.42 h60
  text "Round" at 7378.86,2388.42 h60
  text "Top Layer - Bottom Layer" at 7754.02,2388.42 h60
  text "2" at 6151.16,2264.1 h60
  text "43.31mil (1.100mm)" at 6483.16,2264.1 h60
  text "PTH" at 7119.72,2264.1 h60
  text "Round" at 7378.86,2264.1 h60
  text "Top Layer - Bottom Layer" at 7754.02,2264.1 h60
  text "8" at 6151.16,2139.78 h60
  text "47.24mil (1.200mm)" at 6483.16,2139.78 h60
  text "PTH" at 7119.72,2139.78 h60
  text "Round" at 7378.86,2139.78 h60
  text "Top Layer - Bottom Layer" at 7754.02,2139.78 h60
  text "4" at 6151.16,2015.46 h60
  text "49.21mil (1.250mm)" at 6483.16,2015.46 h60
  text "PTH" at 7119.72,2015.46 h60
  text "Round" at 7378.86,2015.46 h60
  text "Top Layer - Bottom Layer" at 7754.02,2015.46 h60
  text "B" at 5825.31,2005.47 h55.25
  text "3" at 6151.16,1891.14 h60
  text "63.00mil (1.600mm)" at 6483.16,1891.14 h60
  text "PTH" at 7119.72,1891.14 h60
  text "Round" at 7378.86,1891.14 h60
  text "Top Layer - Bottom Layer" at 7754.02,1891.14 h60
  text "2" at 6151.16,1766.82 h60
  text "78.74mil (2.000mm)" at 6483.16,1766.82 h60
  text "PTH" at 7119.72,1766.82 h60
  text "Round" at 7378.86,1766.82 h60
  text "Top Layer - Bottom Layer" at 7754.02,1766.82 h60
  text "219 Total" at 6151.16,1642.5 h60
  text ".Layer_Name" at 577,-858.49 h60
M17 Embedded Cavity:
  text ".Layer_Name" at 577,-858.49 h60
M18 Embedded Assembly:
  text ".Layer_Name" at 577,-858.49 h60
M19 Embedded Keepout:
  text ".Layer_Name" at 577,-858.49 h60

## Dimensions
0,0 to 5551.18,0 on M2 Board Dimensions
0,0 to 0,2125.98 on M2 Board Dimensions
0,-400 to 1000,-400 on M2 Board Dimensions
